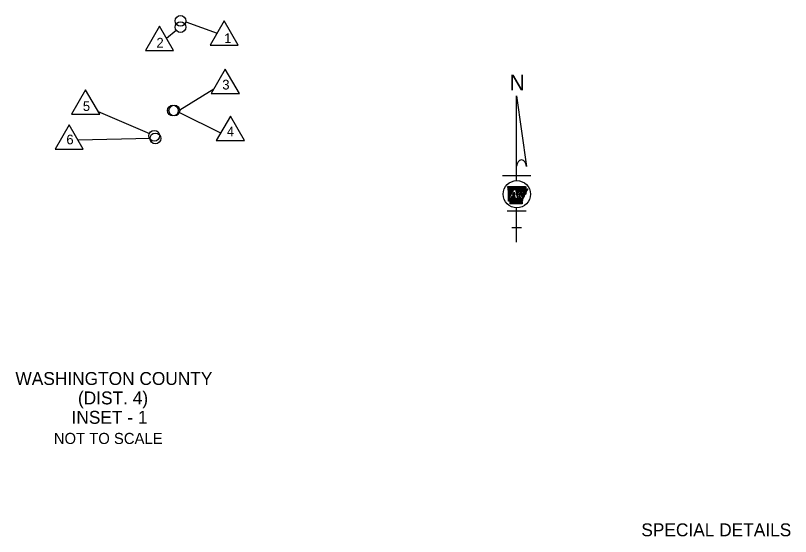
# Model space of a CAD drawing. Extents: x -17668 to 16999, y -17303 to 5867.
# Drawn here: x -9311 to -2121, y -4303 to 529 of the extents above; entities that cross this region are included whole.
import ezdxf

# ---------------------------------------------------------------- set-up
doc = ezdxf.new("R2010")
doc.units = 0
doc.layers.add('48', color=7, linetype='Continuous')

msp = doc.modelspace()

# ---------------------------------------------------------------- linework, layer by layer
at = {"layer": '48'}
for p, q in [((-7730.6, 471.6), (-7441, 366.4)), ((-7375.7, 479.5), (-7506.3, 253.3)), ((-7245, 253.3), (-7375.7, 479.5)), ((-7975.4, 430.4), (-8106, 204.2)), ((-7844.8, 204.2), (-7975.4, 430.4)), ((-7819, 390.5), (-7910.5, 316.9)), ((-7506.3, 253.3), (-7245, 253.3)), ((-8106, 204.2), (-7844.8, 204.2)), ((-7364.2, 31.3), (-7494.8, -194.9)), ((-7233.6, -194.9), (-7364.2, 31.3)), ((-8660.2, -159.9), (-8790.8, -386.1)), ((-8529.6, -386.1), (-8660.2, -159.9)), ((-7787.6, -345.7), (-7470.4, -151.9)), ((-7494.8, -194.9), (-7233.6, -194.9)), ((-4662.1, -214.3), (-4571.2, -871.3)), ((-4662.1, -1002.2), (-4662.1, -214.3)), ((-8790.8, -386.1), (-8529.6, -386.1)), ((-8544.2, -360.9), (-8069.1, -566.3)), ((-7790.4, -369.5), (-7409, -559.1)), ((-7317.7, -404), (-7448.3, -630.2)), ((-7187.1, -630.2), (-7317.7, -404)), ((-8813.5, -484.3), (-8944.1, -710.5)), ((-8682.9, -710.5), (-8813.5, -484.3)), ((-8727.9, -624), (-8062.8, -606.8)), ((-7448.3, -630.2), (-7187.1, -630.2)), ((-8944.1, -710.5), (-8682.9, -710.5)), ((-4793.7, -953.5), (-4530.5, -953.5)), ((-4741.9, -1058.7), (-4740.8, -1057.6)), ((-4741.5, -1061.8), (-4737.3, -1057.6)), ((-4741.1, -1064.9), (-4733.9, -1057.6)), ((-4740.8, -1068), (-4730.4, -1057.6)), ((-4740.4, -1071.1), (-4726.9, -1057.6)), ((-4740, -1074.1), (-4723.4, -1057.6)), ((-4739.6, -1077.2), (-4719.9, -1057.6)), ((-4739.2, -1080.3), (-4716.5, -1057.6)), ((-4738.8, -1083.4), (-4713, -1057.6)), ((-4738.4, -1086.5), (-4709.5, -1057.6)), ((-4738.1, -1089.6), (-4706, -1057.6)), ((-4737.7, -1092.7), (-4702.5, -1057.6)), ((-4737.3, -1095.8), (-4699.1, -1057.6)), ((-4736.9, -1098.9), (-4695.6, -1057.6)), ((-4736.8, -1133.6), (-4660.7, -1057.5)), ((-4736.7, -1130), (-4664.2, -1057.5)), ((-4736.5, -1126.4), (-4667.7, -1057.5)), ((-4736.5, -1102), (-4692.1, -1057.6)), ((-4736.4, -1122.8), (-4671.1, -1057.6)), ((-4736.3, -1119.2), (-4674.6, -1057.6)), ((-4736.2, -1115.6), (-4678.1, -1057.6)), ((-4736.1, -1112), (-4681.6, -1057.6)), ((-4736.1, -1105.1), (-4688.6, -1057.6)), ((-4735.9, -1108.4), (-4685.1, -1057.6)), ((-4685.1, -1085.4), (-4657.2, -1057.5)), ((-4681.6, -1085.4), (-4653.7, -1057.5)), ((-4678.1, -1085.4), (-4650.2, -1057.5)), ((-4674.6, -1085.4), (-4646.6, -1057.4)), ((-4672.4, -1086.7), (-4643.1, -1057.4)), ((-4671.8, -1089.6), (-4639.6, -1057.3)), ((-4671.2, -1092.5), (-4636, -1057.3)), ((-4670.6, -1095.3), (-4632.5, -1057.2)), ((-4670, -1098.2), (-4629, -1057.2)), ((-4669.4, -1101.1), (-4625.4, -1057.1)), ((-4668.8, -1103.9), (-4621.9, -1057.1)), ((-4668.1, -1106.8), (-4618.3, -1057)), ((-4667.5, -1109.7), (-4614.8, -1056.9)), ((-4666.9, -1112.5), (-4611.3, -1056.9)), ((-4666.3, -1115.4), (-4607.7, -1056.8)), ((-4665.7, -1118.3), (-4604.2, -1056.8)), ((-4665.1, -1121.1), (-4600.6, -1056.7)), ((-4664.5, -1124), (-4597.1, -1056.6)), ((-4640.3, -1103.3), (-4593.5, -1056.5)), ((-4636.8, -1103.3), (-4589.9, -1056.5)), ((-4633.3, -1103.3), (-4586.4, -1056.4)), ((-4629.8, -1103.3), (-4582.8, -1056.3)), ((-4626.3, -1103.3), (-4579.2, -1056.2)), ((-4622.9, -1103.3), (-4578.5, -1058.9)), ((-4619.4, -1103.3), (-4576.8, -1060.7)), ((-4615.9, -1103.3), (-4576.3, -1063.8)), ((-4612.4, -1103.3), (-4584.3, -1075.2)), ((-4601.8, -1113.6), (-4566.6, -1078.4)), ((-4737.7, -1162.5), (-4721.7, -1146.4)), ((-4737.6, -1158.9), (-4717.2, -1138.4)), ((-4737.5, -1155.3), (-4712.6, -1130.4)), ((-4737.4, -1151.6), (-4708.1, -1122.4)), ((-4737.3, -1148), (-4703.5, -1114.3)), ((-4737.1, -1144.4), (-4699, -1106.3)), ((-4737, -1140.8), (-4694.4, -1098.3)), ((-4736.9, -1137.2), (-4689.9, -1090.2)), ((-4735.7, -1171.2), (-4687.2, -1085.4)), ((-4700, -1137.5), (-4684.1, -1109.5)), ((-4700, -1137.5), (-4678.1, -1137.5)), ((-4699.8, -1137.5), (-4681.9, -1119.6)), ((-4696.4, -1137.5), (-4681.3, -1122.5)), ((-4695.7, -1129.9), (-4682.6, -1116.8)), ((-4692.9, -1137.5), (-4680.7, -1125.4)), ((-4691.1, -1121.9), (-4683.2, -1113.9)), ((-4689.4, -1137.5), (-4680.1, -1128.2)), ((-4687.2, -1085.4), (-4672.7, -1085.4)), ((-4686.6, -1113.8), (-4683.8, -1111)), ((-4685.9, -1137.5), (-4679.5, -1131.1)), ((-4682.4, -1137.5), (-4678.9, -1134)), ((-4678.9, -1137.5), (-4678.3, -1136.8)), ((-4663.8, -1126.9), (-4644.1, -1107.1)), ((-4663.2, -1129.7), (-4644.8, -1111.3)), ((-4662.6, -1132.6), (-4645.6, -1115.6)), ((-4662, -1135.5), (-4646.3, -1119.8)), ((-4661.4, -1138.4), (-4647, -1124)), ((-4660.8, -1141.2), (-4647.8, -1128.2)), ((-4660.2, -1144.1), (-4648.5, -1132.4)), ((-4659.5, -1147), (-4649.2, -1136.6)), ((-4658.9, -1149.8), (-4650, -1140.9)), ((-4658.3, -1152.7), (-4650.7, -1145.1)), ((-4657.7, -1155.6), (-4651.4, -1149.3)), ((-4643.4, -1103.3), (-4609.7, -1103.3)), ((-4640.6, -1159.3), (-4630.2, -1148.9)), ((-4639.8, -1155.1), (-4631.1, -1146.4)), ((-4639.1, -1150.9), (-4632.1, -1143.9)), ((-4638.3, -1146.7), (-4635.6, -1143.9)), ((-4632, -1143.9), (-4637.9, -1143.9)), ((-4636.1, -1133.7), (-4617.8, -1115.4)), ((-4636.1, -1133.7), (-4621.6, -1133.7)), ((-4635.4, -1129.5), (-4621.2, -1115.4)), ((-4634.6, -1125.3), (-4624.7, -1115.4)), ((-4633.9, -1121.1), (-4628.2, -1115.4)), ((-4633.2, -1116.9), (-4631.7, -1115.4)), ((-4632.9, -1115.4), (-4617.1, -1115.4)), ((-4632.6, -1133.7), (-4615.8, -1117)), ((-4621.9, -1171.2), (-4632, -1143.9)), ((-4629.1, -1133.7), (-4614.6, -1119.3)), ((-4625.6, -1133.7), (-4614, -1122.1)), ((-4622.1, -1133.7), (-4614.3, -1125.9)), ((-4617.7, -1142.5), (-4607.1, -1171.2)), ((-4617.5, -1143.2), (-4616.4, -1142.1)), ((-4616.5, -1145.7), (-4609.9, -1139.1)), ((-4615.6, -1148.3), (-4577, -1109.7)), ((-4614.6, -1150.8), (-4576.3, -1112.5)), ((-4613.7, -1153.4), (-4575.7, -1115.3)), ((-4612.8, -1155.9), (-4575, -1118.2)), ((-4611.8, -1158.5), (-4590.9, -1137.6)), ((-4610.9, -1161), (-4591.3, -1141.4)), ((-4610, -1163.5), (-4591.7, -1145.3)), ((-4609.2, -1103.6), (-4585, -1079.4)), ((-4607.3, -1105.2), (-4581.3, -1079.2)), ((-4605.6, -1107), (-4577.6, -1079)), ((-4604.2, -1133.4), (-4577.6, -1106.8)), ((-4604.1, -1109), (-4574, -1078.8)), ((-4602.8, -1111.1), (-4570.3, -1078.6)), ((-4601.2, -1126.9), (-4569.6, -1095.3)), ((-4601, -1116.2), (-4563.3, -1078.6)), ((-4600.5, -1119.3), (-4561.7, -1080.4)), ((-4600.5, -1122.7), (-4570, -1092.2)), ((-4586.9, -1133.5), (-4582, -1128.7)), ((-4573.5, -1102.7), (-4569.2, -1098.4)), ((-4563.2, -1085.5), (-4560.1, -1082.3)), ((-4738.5, -1187.6), (-4722.1, -1171.2)), ((-4738.5, -1184.1), (-4725.6, -1171.2)), ((-4738.3, -1180.5), (-4729.1, -1171.2)), ((-4738.2, -1176.9), (-4732.5, -1171.2)), ((-4738.1, -1173.3), (-4735.4, -1170.5)), ((-4738, -1169.7), (-4730.8, -1162.5)), ((-4737.9, -1166.1), (-4726.3, -1154.5)), ((-4737.2, -1189.8), (-4700.6, -1153.2)), ((-4719.1, -1171.2), (-4735.7, -1171.2)), ((-4735.1, -1191.2), (-4697.1, -1153.2)), ((-4732.6, -1192.2), (-4693.6, -1153.2)), ((-4728.5, -1191.5), (-4690.2, -1153.2)), ((-4725, -1191.5), (-4686.7, -1153.2)), ((-4722.2, -1192.2), (-4683.2, -1153.2)), ((-4722.1, -1199.1), (-4676.2, -1153.2)), ((-4722.1, -1195.6), (-4679.7, -1153.2)), ((-4722.1, -1202.6), (-4674.4, -1154.8)), ((-4722.1, -1206), (-4673.8, -1157.7)), ((-4722.1, -1209.5), (-4673.2, -1160.6)), ((-4722.1, -1213), (-4672.6, -1163.5)), ((-4722, -1216.4), (-4671.9, -1166.3)), ((-4708.9, -1153.2), (-4719.1, -1171.2)), ((-4718.5, -1216.4), (-4671.3, -1169.2)), ((-4715.1, -1164.2), (-4704.1, -1153.2)), ((-4715.1, -1216.4), (-4669.9, -1171.2)), ((-4711.6, -1216.4), (-4666.4, -1171.2)), ((-4710.6, -1156.2), (-4707.6, -1153.2)), ((-4674.8, -1153.2), (-4708.9, -1153.2)), ((-4708.1, -1216.4), (-4662.9, -1171.2)), ((-4704.6, -1216.4), (-4659.4, -1171.2)), ((-4701.2, -1216.4), (-4655.9, -1171.2)), ((-4697.7, -1216.4), (-4652.4, -1171.2)), ((-4694.2, -1216.4), (-4649, -1171.2)), ((-4690.7, -1216.5), (-4645.5, -1171.2)), ((-4687.3, -1216.5), (-4627.4, -1156.6)), ((-4683.8, -1216.5), (-4626.4, -1159.1)), ((-4680.3, -1216.5), (-4625.5, -1161.6)), ((-4676.8, -1216.5), (-4624.5, -1164.2)), ((-4673.3, -1216.5), (-4623.6, -1166.7)), ((-4642.6, -1171.2), (-4670.9, -1171.2)), ((-4669.9, -1216.5), (-4622.7, -1169.3)), ((-4666.4, -1216.5), (-4621.1, -1171.2)), ((-4662.9, -1216.5), (-4617.6, -1171.2)), ((-4659.4, -1216.5), (-4614.1, -1171.2)), ((-4657.1, -1158.4), (-4652.2, -1153.5)), ((-4656.5, -1161.3), (-4652.9, -1157.7)), ((-4656, -1216.5), (-4610.6, -1171.2)), ((-4655.9, -1164.2), (-4653.6, -1161.9)), ((-4655.3, -1167), (-4654.4, -1166.2)), ((-4652.5, -1216.5), (-4609.5, -1173.5)), ((-4649, -1216.5), (-4609.3, -1176.8)), ((-4645.5, -1216.5), (-4609.2, -1180.2)), ((-4642.1, -1216.5), (-4609, -1183.5)), ((-4642, -1167.7), (-4628.3, -1154)), ((-4641.3, -1163.5), (-4629.2, -1151.5)), ((-4638.6, -1216.5), (-4614.7, -1192.7)), ((-4635.1, -1216.5), (-4613.7, -1195.1)), ((-4631.6, -1216.6), (-4612.6, -1197.5)), ((-4628.1, -1216.6), (-4611.5, -1199.9)), ((-4624.7, -1216.6), (-4610.4, -1202.3)), ((-4607.1, -1171.2), (-4621.9, -1171.2)), ((-4621.2, -1216.6), (-4609.5, -1204.9)), ((-4617.7, -1216.6), (-4611.1, -1210)), ((-4614.2, -1216.6), (-4612.7, -1215)), ((-4609, -1166.1), (-4598.3, -1155.4)), ((-4608.1, -1168.6), (-4599.8, -1160.4)), ((-4749.8, -1281.4), (-4574.4, -1281.4)), ((-4662.1, -1574.1), (-4662.1, -1254.3)), ((-4706, -1437.2), (-4618.2, -1437.2))]:
    msp.add_line(p, q, dxfattribs=at)
for points in [[(-4742.1, -1057.6), (-4694, -1057.6), (-4651.8, -1057.5), (-4602.1, -1056.8), (-4579, -1056.2)], [(-4736.7, -1132.3), (-4735.9, -1107), (-4742.1, -1057.6)], [(-4742, -1057.6), (-4694, -1057.6), (-4651.8, -1057.5), (-4602.1, -1056.7), (-4579, -1056.2)], [(-4738.6, -1187.6), (-4735.9, -1107), (-4742, -1057.6)], [(-4563.9, -1078.3), (-4559.8, -1082.6), (-4570.1, -1091.2), (-4569, -1099.8), (-4577.9, -1105.6), (-4574.9, -1118.8), (-4581.7, -1125.1), (-4582.3, -1131.9), (-4590.7, -1134.9), (-4592, -1147.7), (-4598, -1154.1), (-4600.8, -1163.8), (-4609.6, -1171.8), (-4608.9, -1185.9), (-4614.8, -1192.5), (-4609.4, -1204.6), (-4613.2, -1216.6)], [(-4586.2, -1079.4), (-4563.6, -1078.3)], [(-4586.2, -1079.4), (-4563.6, -1078.3)], [(-4738.6, -1187.6), (-4736.7, -1132.3)], [(-4684.1, -1109.5), (-4678.1, -1137.5)], [(-4672.7, -1085.4), (-4654.9, -1168.9), (-4643.4, -1103.3)], [(-4637.9, -1143.9), (-4642.6, -1171.2)], [(-4636.1, -1133.7), (-4632.9, -1115.4)], [(-4613.2, -1216.6), (-4722.1, -1216.4), (-4722.1, -1192.4)], [(-4613.2, -1216.6), (-4722.1, -1216.4), (-4722.1, -1192.4)], [(-4670.9, -1171.2), (-4674.8, -1153.2)]]:
    msp.add_lwpolyline(points, dxfattribs=at)
for centre in [(-7780, 479.4), (-7780, 421.8), (-7850.7, -352), (-7837.2, -352), (-8023.2, -586.2), (-8013, -610.7)]:
    msp.add_circle(centre, 50, dxfattribs=at)
for centre, major_axis, ratio, start_param, end_param in [((-4616.7, -872.8), (-1.9, 63.2), 0.719778, 4.712385, 7.768526), ((-4625.1, -1123.1), (-11.1, 0), 0.999987, 1.887169, 3.90762), ((-4622.2, -1121.1), (-21.8, 0), 0.999987, 1.777838, 4.099264)]:
    msp.add_ellipse(centre, major_axis=major_axis, ratio=ratio, start_param=start_param, end_param=end_param, dxfattribs=at)
msp.add_ellipse((-4660, -1128.2), major_axis=(126, 0), ratio=0.999976, dxfattribs=at)
for points in [[(-4579, -1056.2), (-4578.9, -1057.5), (-4578.5, -1058.2), (-4578.4, -1059.5), (-4577.9, -1060), (-4577, -1060.5), (-4576.3, -1061.4), (-4576.1, -1062.4), (-4576.3, -1063.4), (-4576.4, -1064.6), (-4576.5, -1065.6), (-4576.7, -1066.5), (-4577.4, -1067.3), (-4578.1, -1067.8), (-4578.7, -1068.4), (-4579.1, -1069.1), (-4579.9, -1069.8), (-4580.7, -1070.5), (-4581.3, -1071.2), (-4581.9, -1072), (-4582.2, -1072.9), (-4582.9, -1073.6), (-4583.5, -1074.2), (-4584.2, -1075), (-4584.5, -1075.8), (-4585.2, -1076.7), (-4585.4, -1077.6), (-4585.8, -1078.3), (-4585.8, -1078.4)], [(-4579, -1056.2), (-4578.9, -1057.5), (-4578.5, -1058.2), (-4578.4, -1059.4), (-4577.9, -1060), (-4577, -1060.5), (-4576.3, -1061.4), (-4576.1, -1062.4), (-4576.3, -1063.4), (-4576.4, -1064.6), (-4576.5, -1065.6), (-4576.7, -1066.5), (-4577.4, -1067.3), (-4578.1, -1067.8), (-4578.7, -1068.4), (-4579.1, -1069.1), (-4579.9, -1069.8), (-4580.7, -1070.5), (-4581.3, -1071.2), (-4581.9, -1072), (-4582.2, -1072.9), (-4582.9, -1073.6), (-4583.5, -1074.2), (-4584.2, -1075), (-4584.5, -1075.8), (-4585.2, -1076.7), (-4585.4, -1077.6), (-4585.8, -1078.3), (-4585.8, -1078.4)], [(-4563.9, -1078.3), (-4563.6, -1078.3), (-4562.6, -1079.3), (-4562.2, -1080.2), (-4561.5, -1080.7), (-4560.7, -1081), (-4560.2, -1081.7), (-4559.8, -1082.4), (-4560, -1083.1), (-4560.8, -1083.1), (-4561.8, -1083.3), (-4562.7, -1083.2), (-4563.4, -1083.9), (-4562.7, -1084.6), (-4561.9, -1085.4), (-4561.6, -1086.2), (-4562.1, -1087), (-4563, -1087.4), (-4564, -1087.8), (-4564.8, -1088.4), (-4565.2, -1089.1), (-4566.1, -1089.4), (-4567.1, -1089.7), (-4567.9, -1089.8), (-4568.8, -1090), (-4569.7, -1090.4), (-4570.1, -1091.2), (-4570, -1092.3), (-4570, -1093.4), (-4569.1, -1093.8), (-4568.2, -1093.9), (-4567.4, -1094.3), (-4567.5, -1095), (-4568.1, -1095.8), (-4568.8, -1096.4), (-4569.6, -1096.8), (-4570.3, -1097.4), (-4570, -1098), (-4569.4, -1098.4), (-4569, -1099.1), (-4569, -1099.7), (-4569.7, -1100.2), (-4570.5, -1100), (-4571.1, -1099.3), (-4571.7, -1099), (-4572.3, -1098.8), (-4572.9, -1099.1), (-4572.9, -1100), (-4573.2, -1100.9), (-4573, -1101.6), (-4572.7, -1102.6), (-4572.7, -1103.3), (-4573, -1104.3), (-4573.5, -1105.3), (-4574, -1105.7), (-4574.3, -1104.5), (-4574.4, -1103.6), (-4574.8, -1103.1), (-4575.3, -1103), (-4575.9, -1103.5), (-4576.6, -1104.2), (-4577.4, -1104.9), (-4577.9, -1105.7), (-4577.7, -1106.6), (-4577, -1106.8), (-4576.5, -1106.6), (-4576.2, -1106), (-4575.8, -1106), (-4575.3, -1106.9)], [(-4588.2, -1136.3), (-4589.2, -1137.1), (-4589.7, -1137.9), (-4592.3, -1137.7), (-4592.2, -1138.6), (-4593.2, -1139.1), (-4594, -1139.7), (-4593.5, -1140.4), (-4592.6, -1141.1), (-4591.7, -1141.6), (-4591.2, -1142.1), (-4591, -1143.3), (-4590.9, -1144.1), (-4590.6, -1145.2), (-4590.5, -1145.9), (-4591, -1146.8), (-4591.6, -1147), (-4592.3, -1146.8), (-4593, -1146.7), (-4593.7, -1147.3), (-4594.1, -1148.1), (-4594.6, -1149), (-4594.9, -1149.7), (-4595.2, -1150.5), (-4595.9, -1151.4), (-4596.7, -1151.5), (-4597.6, -1151.7), (-4598.2, -1152.4), (-4598.1, -1153.5), (-4597.6, -1154.2), (-4597.1, -1155.1), (-4596.9, -1155.9), (-4597, -1156.9), (-4597.4, -1157.7), (-4597.9, -1158.2), (-4598.2, -1159.1), (-4598.6, -1159.8), (-4598.9, -1160), (-4599.6, -1160), (-4600.4, -1159.8), (-4601.1, -1159.9), (-4601.7, -1160.2), (-4602.3, -1160), (-4603, -1159.3), (-4603.5, -1158.8), (-4604.1, -1158.6), (-4604.7, -1158.9), (-4604.8, -1159.9), (-4604.5, -1160.9), (-4604.3, -1162.2), (-4604.5, -1163.1), (-4604.6, -1164.5)], [(-4575.3, -1106.9), (-4575.1, -1107.7), (-4575.6, -1108.6), (-4575.8, -1109.6), (-4575.8, -1110.5), (-4576.7, -1111), (-4577.5, -1111.6), (-4577, -1112.3), (-4576.1, -1113), (-4575.3, -1113.5), (-4574.7, -1114), (-4574.6, -1115.2), (-4574.4, -1116), (-4574.1, -1117), (-4574, -1117.8), (-4574.5, -1118.7), (-4575.1, -1118.9), (-4575.8, -1118.7), (-4576.6, -1118.6), (-4577.2, -1119.2), (-4577.6, -1120), (-4578.1, -1120.8), (-4578.4, -1121.6), (-4578.7, -1122.3), (-4579.4, -1123.2), (-4580.2, -1123.4), (-4581.1, -1123.6), (-4581.7, -1124.3), (-4581.6, -1125.4), (-4581.1, -1126.1), (-4580.7, -1127), (-4580.4, -1127.8), (-4580.5, -1128.8), (-4580.9, -1129.6), (-4581.5, -1130), (-4581.7, -1131), (-4582.1, -1131.7), (-4582.4, -1131.9), (-4583.2, -1131.9), (-4583.9, -1131.7), (-4584.6, -1131.8), (-4585.2, -1132.1), (-4585.8, -1131.9), (-4586.5, -1131.2), (-4587, -1130.6), (-4587.6, -1130.4), (-4588.2, -1130.8), (-4588.3, -1131.8), (-4588, -1132.8), (-4587.8, -1134.1), (-4588, -1134.9), (-4588.2, -1136.3)], [(-4722.1, -1192.4), (-4722, -1192.4), (-4722.6, -1192), (-4723.4, -1191.7), (-4724.2, -1191.6), (-4725.3, -1191.5), (-4726.2, -1191.4), (-4727.2, -1190.7), (-4728.2, -1191.4), (-4729.3, -1191.9), (-4730, -1191.3), (-4730.8, -1191.7), (-4731.4, -1191.5), (-4732.5, -1192.2), (-4733.5, -1191.9), (-4734.2, -1192.1), (-4735.1, -1192.1), (-4735.2, -1191.1), (-4736.1, -1191), (-4736.9, -1190.5), (-4737.3, -1189.5), (-4737.7, -1188.7), (-4738.6, -1187.6)], [(-4722.1, -1192.4), (-4722, -1192.4), (-4722.6, -1192), (-4723.4, -1191.7), (-4724.2, -1191.6), (-4725.3, -1191.4), (-4726.2, -1191.4), (-4727.2, -1190.7), (-4728.2, -1191.4), (-4729.3, -1191.9), (-4730, -1191.3), (-4730.8, -1191.7), (-4731.4, -1191.5), (-4732.5, -1192.2), (-4733.5, -1191.9), (-4734.2, -1192.2), (-4735.1, -1192.1), (-4735.2, -1191.1), (-4736.1, -1191), (-4736.8, -1190.6), (-4737.4, -1189.5), (-4737.7, -1188.7), (-4738.6, -1187.6)], [(-4608.6, -1175.6), (-4608.9, -1176.3), (-4609.3, -1177.5), (-4609.2, -1178.5), (-4608.7, -1179.4), (-4608, -1179.8), (-4607.2, -1180.5), (-4607.3, -1181.6), (-4607.7, -1182), (-4608.8, -1181.7), (-4609.6, -1181.3), (-4610.3, -1181.5), (-4611.2, -1182), (-4611.9, -1182.1), (-4611.8, -1183.5), (-4610.9, -1184.5), (-4610.1, -1184.5), (-4609.2, -1184.6), (-4608.9, -1185.7), (-4609.4, -1186.6), (-4610.3, -1187), (-4611.4, -1186.5), (-4612.2, -1185.9), (-4613, -1185.4), (-4614, -1185.1), (-4614.6, -1185.3), (-4614.9, -1186.5), (-4614.4, -1187.6), (-4613.6, -1188.4), (-4612.9, -1189.4), (-4613, -1190.2), (-4613.6, -1190.4), (-4614.5, -1190.6), (-4615.1, -1190.9), (-4615.2, -1191.1), (-4614.9, -1192.1), (-4614.7, -1193.2), (-4614.7, -1194.1), (-4615, -1194.8), (-4615.5, -1196), (-4615.4, -1196.8), (-4615.1, -1197.1), (-4614.6, -1197), (-4614, -1196.6), (-4613.6, -1196.1), (-4613.3, -1195.5), (-4612.7, -1195), (-4611.9, -1195.5), (-4611.7, -1196.4), (-4612.2, -1197.2), (-4612.8, -1197.6), (-4613.6, -1197.9), (-4614.2, -1198.5), (-4614, -1199.3), (-4613.6, -1199.7), (-4612.4, -1199.5), (-4611.7, -1199.2), (-4611.3, -1198.8), (-4610.8, -1198.3), (-4610.5, -1197.7), (-4610.1, -1197.2), (-4609.4, -1197.1), (-4609.1, -1197.5), (-4609.3, -1198.5), (-4609.7, -1199.5), (-4610.2, -1200.3), (-4610.9, -1200.8), (-4611.6, -1202), (-4611.5, -1203.2), (-4611.2, -1204.1), (-4610.8, -1204.8), (-4610.1, -1204.7), (-4609.3, -1204.6), (-4608.8, -1205), (-4608.8, -1205.8), (-4609.4, -1206.6), (-4610, -1207.4), (-4610.3, -1208.4), (-4610.2, -1209.2), (-4610.2, -1209.9), (-4610.4, -1210.6), (-4610.8, -1211), (-4611.9, -1211), (-4613.1, -1210.9), (-4613.7, -1211.2), (-4613.6, -1212.2), (-4612.9, -1213), (-4612.4, -1213.4), (-4611.7, -1214.2), (-4611.5, -1214.9), (-4611.5, -1215.5), (-4612, -1216), (-4613.2, -1216.6)], [(-4608.6, -1175.6), (-4608.9, -1176.3), (-4609.3, -1177.5), (-4609.2, -1178.5), (-4608.7, -1179.4), (-4608, -1179.8), (-4607.2, -1180.5), (-4607.3, -1181.6), (-4607.7, -1182), (-4608.8, -1181.7), (-4609.6, -1181.3), (-4610.3, -1181.5), (-4611.2, -1182), (-4611.9, -1182.1), (-4611.8, -1183.5), (-4610.9, -1184.5), (-4610.1, -1184.5), (-4609.2, -1184.6), (-4608.9, -1185.7), (-4609.4, -1186.6), (-4610.3, -1187), (-4611.4, -1186.5), (-4612.2, -1185.9), (-4613, -1185.4), (-4614, -1185.1), (-4614.6, -1185.3), (-4614.9, -1186.5), (-4614.4, -1187.6), (-4613.6, -1188.4), (-4612.9, -1189.4), (-4613, -1190.2), (-4613.6, -1190.4), (-4614.5, -1190.6), (-4615.1, -1190.9), (-4615.2, -1191.1), (-4614.9, -1192.1), (-4614.7, -1193.2), (-4614.7, -1194.1), (-4615, -1194.8), (-4615.5, -1196), (-4615.4, -1196.8), (-4615.1, -1197.1), (-4614.6, -1197), (-4614, -1196.6), (-4613.6, -1196.1), (-4613.3, -1195.5), (-4612.7, -1195), (-4611.9, -1195.5), (-4611.7, -1196.4), (-4612.2, -1197.2), (-4612.8, -1197.6), (-4613.6, -1197.9), (-4614.2, -1198.5), (-4614, -1199.3), (-4613.6, -1199.7), (-4612.4, -1199.5), (-4611.7, -1199.2), (-4611.3, -1198.8), (-4610.8, -1198.3), (-4610.5, -1197.7), (-4610.1, -1197.2), (-4609.4, -1197.1), (-4609.1, -1197.5), (-4609.3, -1198.5), (-4609.7, -1199.5), (-4610.2, -1200.3), (-4610.9, -1200.8), (-4611.6, -1202), (-4611.5, -1203.2), (-4611.2, -1204.1), (-4610.8, -1204.8), (-4610.1, -1204.7), (-4609.3, -1204.6), (-4608.8, -1205), (-4608.8, -1205.8), (-4609.4, -1206.6), (-4610, -1207.4), (-4610.3, -1208.4), (-4610.2, -1209.2), (-4610.2, -1209.9), (-4610.4, -1210.6), (-4610.8, -1211), (-4611.9, -1211), (-4613.1, -1210.9), (-4613.7, -1211.2), (-4613.6, -1212.2), (-4612.9, -1213), (-4612.4, -1213.4), (-4611.7, -1214.2), (-4611.5, -1214.9), (-4611.5, -1215.5), (-4612, -1216), (-4613.2, -1216.6)], [(-4604.6, -1164.5), (-4604.7, -1164.5), (-4605.2, -1165.2), (-4604.9, -1166.2), (-4603.8, -1166.6), (-4603.2, -1167.6), (-4603.2, -1168.5), (-4603.6, -1169.7), (-4604.1, -1170.3), (-4605.2, -1170.6), (-4606, -1170.7), (-4606.1, -1172.1), (-4606.5, -1172.7), (-4607.1, -1173), (-4608, -1172.5), (-4608.5, -1172.3), (-4609.2, -1172), (-4610, -1171.5), (-4610.6, -1171.6), (-4610.4, -1172.9), (-4610.4, -1173), (-4609.7, -1173.9), (-4609, -1174.7), (-4608.6, -1175.6)], [(-4604.6, -1164.5), (-4604.7, -1164.5), (-4605.2, -1165.2), (-4604.9, -1166.2), (-4603.8, -1166.6), (-4603.2, -1167.6), (-4603.2, -1168.5), (-4603.6, -1169.7), (-4604.1, -1170.3), (-4605.2, -1170.6), (-4606, -1170.7), (-4606.1, -1172.1), (-4606.5, -1172.7), (-4607.1, -1173), (-4608, -1172.5), (-4608.5, -1172.3), (-4609.2, -1172), (-4610, -1171.5), (-4610.6, -1171.6), (-4610.4, -1172.9), (-4610.4, -1173), (-4609.7, -1173.9), (-4609, -1174.7), (-4608.6, -1175.6)]]:
    msp.add_spline(points, degree=3, dxfattribs=at)

# ---------------------------------------------------------------- texts
for s, height, p in [('1', 90, (-7374.7, 273.2)), ('2', 90, (-8003.1, 231.9)), ('3', 90, (-7392.1, -156.8)), ('N', 146.7, (-4727.5, -164.7)), ('5', 90, (-8685.7, -355.7)), ('4', 90, (-7349.9, -590.6)), ('6', 90, (-8838.7, -665.5)), ('STS 10-03-17', 3.644, (-4672.1, -1253.3)), ('WASHINGTON COUNTY', 120, (-9311.4, -2897.3)), ('(DIST. 4)', 120, (-8731.3, -3077.3)), ('INSET - 1', 120, (-8790.8, -3257.3)), ('NOT TO SCALE', 102.885, (-8955.3, -3444.5)), ('SPECIAL DETAILS', 120, (-3505.1, -4300.8))]:
    msp.add_text(s, height=height, dxfattribs=at).set_placement(p)

doc.saveas('drawing.dxf')
